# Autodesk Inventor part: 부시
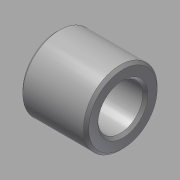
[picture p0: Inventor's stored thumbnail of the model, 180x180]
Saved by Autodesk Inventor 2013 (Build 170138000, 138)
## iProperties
Created: 2016-10
Part Number: 부시
Material: 강철, 연강
Document SubType Name: Modeling
Designer: mduedu
Density: 1 g/cm^3
Author: mduedu
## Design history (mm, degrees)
sketch "스케치1"
  geometry: C1 r 14 at (0, 0); C2 r 8.5 at (0, 0); 1 further point
  constraints: 2 centre point, 2 coincident
  dimensions: "d0" = 28 diameter of C1; "d1" = 17 diameter of C2
extrude "돌출1" new body sketch "스케치1" distance "d2" = 25; taper "d3" = 0 deg
chamfer "모따기1" distance "d4" = 1; stored, may be unused: second distance "d5" = 2, angle "d6" = 45 deg
chamfer "모따기2" distance "d7" = 1; stored, may be unused: second distance "d8" = 2, angle "d9" = 45 deg
node "솔리드1"
